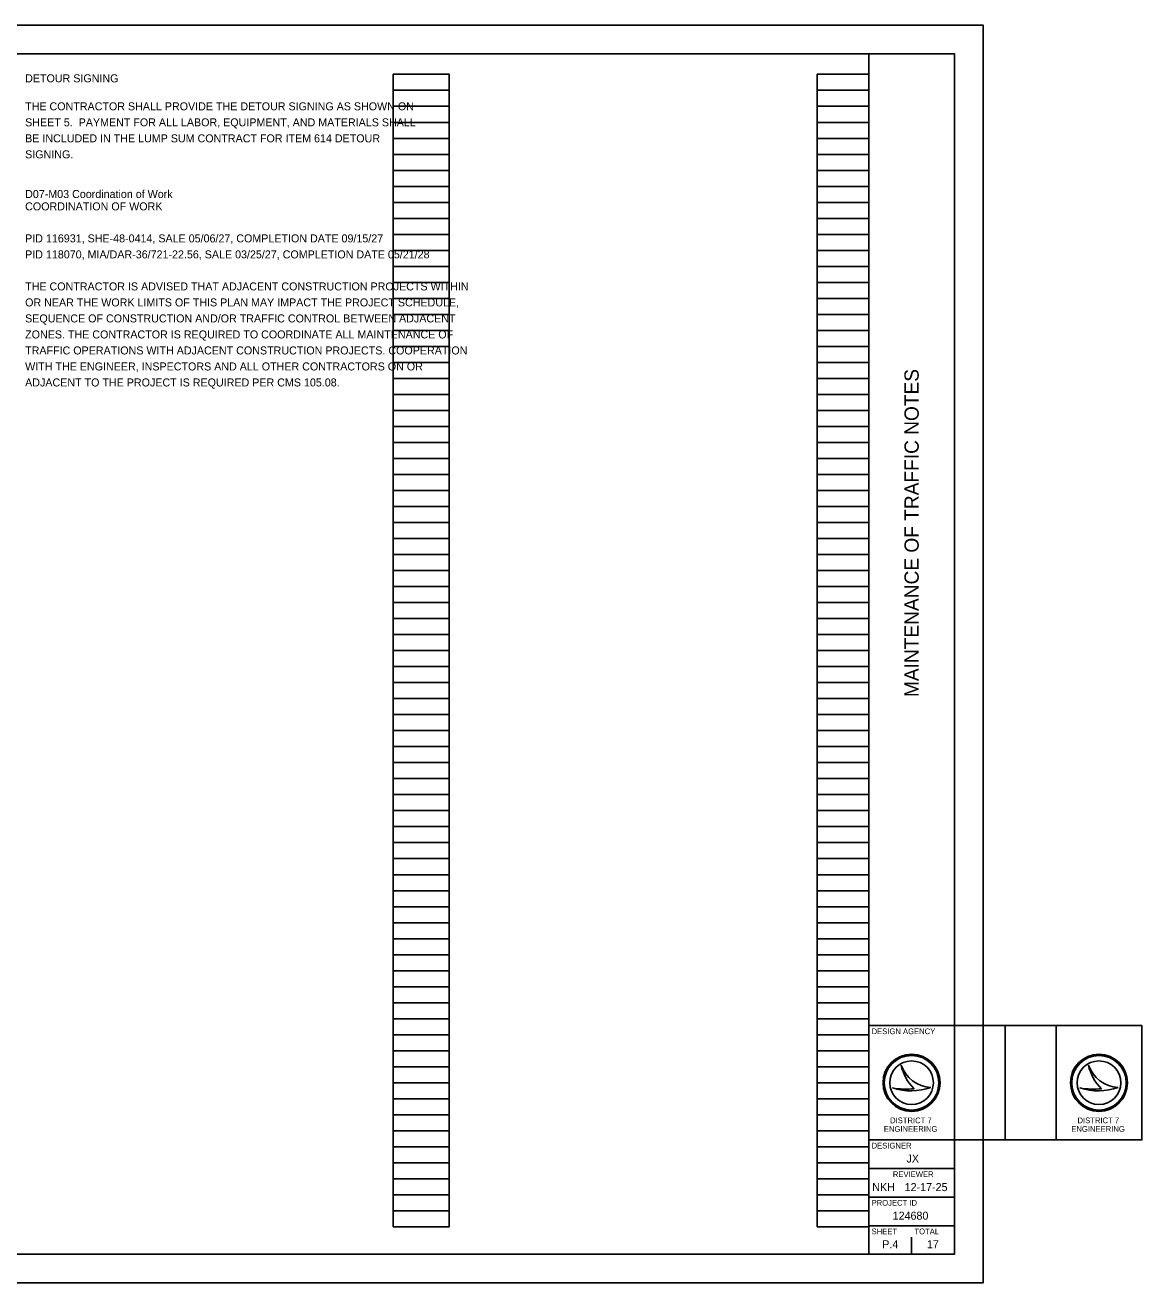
# Model space of a CAD drawing. Extents: x -9 to 36.8, y 0 to 22.
# Drawn here: x 17.24 to 36.78, y 0 to 22 of the extents above; entities that cross this region are included whole.
import ezdxf

# ---------------------------------------------------------------- set-up
doc = ezdxf.new("R2010")
doc.units = 0
for name, color, linetype in [('SC_Scratch1', 7, 'Continuous'), ('SH_Border', 7, 'Continuous'), ('SH_Cut_Line', 7, 'Continuous'), ('SH_Data', 7, 'Continuous'), ('SH_Text', 7, 'Continuous')]:
    doc.layers.add(name, color=color, linetype=linetype)

msp = doc.modelspace()

# ---------------------------------------------------------------- linework, layer by layer
at = {"layer": 'SC_Scratch1'}
for p, q in [((33.5, 4.5), (35.279, 4.5)), ((34.389, 4.5), (34.389, 2.5)), ((35.279, 2.5), (33.5, 2.5))]:
    msp.add_line(p, q, dxfattribs=at)
msp.add_lwpolyline([(35.279, 4.5), (36.779, 4.5), (36.779, 2.5), (35.279, 2.5)], close=True, dxfattribs=at)
at = {"layer": 'SH_Border'}
for p, q in [((32, 0.5), (32, 21.5)), ((32, 4.5), (33.5, 4.5)), ((32, 2.5), (33.5, 2.5)), ((32, 2), (33.5, 2)), ((32, 1.5), (33.5, 1.5)), ((32, 1), (33.5, 1))]:
    msp.add_line(p, q, dxfattribs=at)
msp.add_lwpolyline([(1.5, 21.5), (33.5, 21.5), (33.5, 0.5), (1.5, 0.5)], close=True, dxfattribs=at)
at = {"layer": 'SH_Cut_Line'}
msp.add_lwpolyline([(0, 0), (34, 0), (34, 22), (0, 22)], close=True, dxfattribs=at)
at = {"layer": 'SH_Data'}
for p, q in [((23.68, 0.98), (23.68, 21.14)), ((23.68, 21.14), (24.66, 21.14)), ((24.66, 0.98), (24.66, 21.14)), ((31.1, 0.98), (31.1, 21.14)), ((31.1, 21.14), (32, 21.14)), ((32, 0.98), (32, 21.14)), ((23.68, 20.86), (24.66, 20.86)), ((31.1, 20.86), (32, 20.86)), ((23.68, 20.58), (24.66, 20.58)), ((31.1, 20.58), (32, 20.58)), ((23.68, 20.3), (24.66, 20.3)), ((31.1, 20.3), (32, 20.3)), ((23.68, 20.02), (24.66, 20.02)), ((31.1, 20.02), (32, 20.02)), ((23.68, 19.74), (24.66, 19.74)), ((31.1, 19.74), (32, 19.74)), ((23.68, 19.46), (24.66, 19.46)), ((31.1, 19.46), (32, 19.46)), ((23.68, 19.18), (24.66, 19.18)), ((31.1, 19.18), (32, 19.18)), ((23.68, 18.9), (24.66, 18.9)), ((31.1, 18.9), (32, 18.9)), ((23.68, 18.62), (24.66, 18.62)), ((31.1, 18.62), (32, 18.62)), ((23.68, 18.34), (24.66, 18.34)), ((31.1, 18.34), (32, 18.34)), ((23.68, 18.06), (24.66, 18.06)), ((31.1, 18.06), (32, 18.06)), ((23.68, 17.78), (24.66, 17.78)), ((31.1, 17.78), (32, 17.78)), ((23.68, 17.5), (24.66, 17.5)), ((31.1, 17.5), (32, 17.5)), ((23.68, 17.22), (24.66, 17.22)), ((31.1, 17.22), (32, 17.22)), ((23.68, 16.94), (24.66, 16.94)), ((31.1, 16.94), (32, 16.94)), ((23.68, 16.66), (24.66, 16.66)), ((31.1, 16.66), (32, 16.66)), ((23.68, 16.38), (24.66, 16.38)), ((31.1, 16.38), (32, 16.38)), ((23.68, 16.1), (24.66, 16.1)), ((31.1, 16.1), (32, 16.1)), ((23.68, 15.82), (24.66, 15.82)), ((31.1, 15.82), (32, 15.82)), ((23.68, 15.54), (24.66, 15.54)), ((31.1, 15.54), (32, 15.54)), ((23.68, 15.26), (24.66, 15.26)), ((31.1, 15.26), (32, 15.26)), ((23.68, 14.98), (24.66, 14.98)), ((31.1, 14.98), (32, 14.98)), ((23.68, 14.7), (24.66, 14.7)), ((31.1, 14.7), (32, 14.7)), ((23.68, 14.42), (24.66, 14.42)), ((31.1, 14.42), (32, 14.42)), ((23.68, 14.14), (24.66, 14.14)), ((31.1, 14.14), (32, 14.14)), ((23.68, 13.86), (24.66, 13.86)), ((31.1, 13.86), (32, 13.86)), ((23.68, 13.58), (24.66, 13.58)), ((31.1, 13.58), (32, 13.58)), ((23.68, 13.3), (24.66, 13.3)), ((31.1, 13.3), (32, 13.3)), ((23.68, 13.02), (24.66, 13.02)), ((31.1, 13.02), (32, 13.02)), ((23.68, 12.74), (24.66, 12.74)), ((31.1, 12.74), (32, 12.74)), ((23.68, 12.46), (24.66, 12.46)), ((31.1, 12.46), (32, 12.46)), ((23.68, 12.18), (24.66, 12.18)), ((31.1, 12.18), (32, 12.18)), ((23.68, 11.9), (24.66, 11.9)), ((31.1, 11.9), (32, 11.9)), ((23.68, 11.62), (24.66, 11.62)), ((31.1, 11.62), (32, 11.62)), ((23.68, 11.34), (24.66, 11.34)), ((31.1, 11.34), (32, 11.34)), ((23.68, 11.06), (24.66, 11.06)), ((31.1, 11.06), (32, 11.06)), ((23.68, 10.78), (24.66, 10.78)), ((31.1, 10.78), (32, 10.78)), ((23.68, 10.5), (24.66, 10.5)), ((31.1, 10.5), (32, 10.5)), ((23.68, 10.22), (24.66, 10.22)), ((31.1, 10.22), (32, 10.22)), ((23.68, 9.94), (24.66, 9.94)), ((31.1, 9.94), (32, 9.94)), ((23.68, 9.66), (24.66, 9.66)), ((31.1, 9.66), (32, 9.66)), ((23.68, 9.38), (24.66, 9.38)), ((31.1, 9.38), (32, 9.38)), ((23.68, 9.1), (24.66, 9.1)), ((31.1, 9.1), (32, 9.1)), ((23.68, 8.82), (24.66, 8.82)), ((31.1, 8.82), (32, 8.82)), ((23.68, 8.54), (24.66, 8.54)), ((31.1, 8.54), (32, 8.54)), ((23.68, 8.26), (24.66, 8.26)), ((31.1, 8.26), (32, 8.26)), ((23.68, 7.98), (24.66, 7.98)), ((31.1, 7.98), (32, 7.98)), ((23.68, 7.7), (24.66, 7.7)), ((31.1, 7.7), (32, 7.7)), ((23.68, 7.42), (24.66, 7.42)), ((31.1, 7.42), (32, 7.42)), ((23.68, 7.14), (24.66, 7.14)), ((31.1, 7.14), (32, 7.14)), ((23.68, 6.86), (24.66, 6.86)), ((31.1, 6.86), (32, 6.86)), ((23.68, 6.58), (24.66, 6.58)), ((31.1, 6.58), (32, 6.58)), ((23.68, 6.3), (24.66, 6.3)), ((31.1, 6.3), (32, 6.3)), ((23.68, 6.02), (24.66, 6.02)), ((31.1, 6.02), (32, 6.02)), ((23.68, 5.74), (24.66, 5.74)), ((31.1, 5.74), (32, 5.74)), ((23.68, 5.46), (24.66, 5.46)), ((31.1, 5.46), (32, 5.46)), ((23.68, 5.18), (24.66, 5.18)), ((31.1, 5.18), (32, 5.18)), ((23.68, 4.9), (24.66, 4.9)), ((31.1, 4.9), (32, 4.9)), ((23.68, 4.62), (24.66, 4.62)), ((31.1, 4.62), (32, 4.62)), ((23.68, 4.34), (24.66, 4.34)), ((31.1, 4.34), (32, 4.34)), ((23.68, 4.06), (24.66, 4.06)), ((31.1, 4.06), (32, 4.06)), ((23.68, 3.78), (24.66, 3.78)), ((31.1, 3.78), (32, 3.78)), ((32.567, 3.81), (32.567, 3.81)), ((35.846, 3.81), (35.846, 3.81)), ((23.68, 3.5), (24.66, 3.5)), ((31.1, 3.5), (32, 3.5)), ((32.417, 3.41), (32.417, 3.41)), ((32.75, 3.5), (32.75, 3.5)), ((33.087, 3.419), (33.087, 3.419)), ((35.696, 3.41), (35.696, 3.41)), ((36.366, 3.419), (36.366, 3.419)), ((23.68, 3.22), (24.66, 3.22)), ((31.1, 3.22), (32, 3.22)), ((23.68, 2.94), (24.66, 2.94)), ((31.1, 2.94), (32, 2.94)), ((23.68, 2.66), (24.66, 2.66)), ((31.1, 2.66), (32, 2.66)), ((23.68, 2.38), (24.66, 2.38)), ((31.1, 2.38), (32, 2.38)), ((23.68, 2.1), (24.66, 2.1)), ((31.1, 2.1), (32, 2.1)), ((23.68, 1.82), (24.66, 1.82)), ((31.1, 1.82), (32, 1.82)), ((23.68, 1.54), (24.66, 1.54)), ((31.1, 1.54), (32, 1.54)), ((23.68, 1.26), (24.66, 1.26)), ((31.1, 1.26), (32, 1.26)), ((23.68, 0.98), (24.66, 0.98)), ((31.1, 0.98), (32, 0.98)), ((32.375, 0.675), (32.375, 0.675)), ((32.75, 0.5), (32.75, 0.8))]:
    msp.add_line(p, q, dxfattribs=at)
for centre, radius in [((32.75, 3.5), 0.5), ((32.75, 3.5), 0.477), ((32.75, 3.5), 0.477), ((36.029, 3.5), 0.5), ((36.029, 3.5), 0.477), ((36.029, 3.5), 0.477), ((32.75, 3.5), 0.382), ((36.029, 3.5), 0.382)]:
    msp.add_circle(centre, radius, dxfattribs=at)
for centre, radius, start, end in [((33.116, 3.998), 0.58, 198.9257, 198.9319), ((33.347, 3.97), 0.796, 191.6379, 191.6421), ((33.116, 3.998), 0.58, 198.9319, 267.1657), ((33.347, 3.97), 0.796, 191.6421, 226.0947), ((36.395, 3.998), 0.58, 198.9257, 198.9319), ((36.625, 3.97), 0.796, 191.6379, 191.6421), ((36.395, 3.998), 0.58, 198.9319, 267.1657), ((36.625, 3.97), 0.796, 191.6421, 226.0947), ((32.739, 4.37), 1.013, 251.4576, 290.0832), ((32.648, 4.654), 1.266, 259.4964, 259.4995), ((32.739, 4.37), 1.013, 251.4527, 251.4576), ((32.648, 4.654), 1.266, 259.4995, 276.6672), ((36.018, 4.37), 1.013, 251.4576, 290.0832), ((35.927, 4.654), 1.266, 259.4964, 259.4995), ((36.018, 4.37), 1.013, 251.4527, 251.4576), ((35.927, 4.654), 1.266, 259.4995, 276.6672)]:
    msp.add_arc(centre, radius, start, end, dxfattribs=at)

# ---------------------------------------------------------------- texts
at = {"layer": 'SC_Scratch1'}
msp.add_text('D07-M03 Coordination of Work', height=0.14, dxfattribs=at).set_placement((17.24, 18.976))
at = {"layer": 'SH_Data'}
msp.add_text('MAINTENANCE OF TRAFFIC NOTES', height=0.25, rotation=90, dxfattribs=at).set_placement((32.875, 10.247))
for s, height, p in [('DESIGN AGENCY', 0.1, (32.05, 4.35)), ('DESIGNER', 0.1, (32.05, 2.35)), ('JX', 0.14, (32.661, 2.105)), ('REVIEWER', 0.1, (32.422, 1.85)), ('NKH', 0.14, (32.062, 1.605)), ('12-17-25', 0.14, (32.629, 1.605)), ('PROJECT ID', 0.1, (32.05, 1.35)), ('124680', 0.14, (32.419, 1.105)), ('SHEET', 0.1, (32.05, 0.85)), ('TOTAL', 0.1, (32.8, 0.85)), ('P.4', 0.14, (32.237, 0.605)), ('17', 0.14, (33.018, 0.605))]:
    msp.add_text(s, height=height, dxfattribs=at).set_placement(p)
at = {"layer": 'SH_Text'}
for s, height, p in [('DETOUR SIGNING', 0.14, (17.24, 21)), ('THE CONTRACTOR SHALL PROVIDE THE DETOUR SIGNING AS SHOWN ON ', 0.14, (17.24, 20.51)), ('SHEET 5.  PAYMENT FOR ALL LABOR, EQUIPMENT, AND MATERIALS SHALL ', 0.14, (17.24, 20.23)), ('BE INCLUDED IN THE LUMP SUM CONTRACT FOR ITEM 614 DETOUR ', 0.14, (17.24, 19.95)), ('SIGNING.', 0.14, (17.24, 19.67)), ('COORDINATION OF WORK', 0.14, (17.24, 18.76)), ('PID 116931, SHE-48-0414, SALE 05/06/27, COMPLETION DATE 09/15/27', 0.14, (17.24, 18.2)), ('PID 118070, MIA/DAR-36/721-22.56, SALE 03/25/27, COMPLETION DATE 05/21/28', 0.14, (17.24, 17.92)), ('THE CONTRACTOR IS ADVISED THAT ADJACENT CONSTRUCTION PROJECTS WITHIN ', 0.14, (17.24, 17.36)), ('OR NEAR THE WORK LIMITS OF THIS PLAN MAY IMPACT THE PROJECT SCHEDULE, ', 0.14, (17.24, 17.08)), ('SEQUENCE OF CONSTRUCTION AND/OR TRAFFIC CONTROL BETWEEN ADJACENT ', 0.14, (17.24, 16.8)), ('ZONES. THE CONTRACTOR IS REQUIRED TO COORDINATE ALL MAINTENANCE OF ', 0.14, (17.24, 16.52)), ('TRAFFIC OPERATIONS WITH ADJACENT CONSTRUCTION PROJECTS. COOPERATION ', 0.14, (17.24, 16.24)), ('WITH THE ENGINEER, INSPECTORS AND ALL OTHER CONTRACTORS ON OR ', 0.14, (17.24, 15.96)), ('ADJACENT TO THE PROJECT IS REQUIRED PER CMS 105.08.', 0.14, (17.24, 15.68)), ('DISTRICT 7', 0.1, (32.374, 2.792)), ('DISTRICT 7', 0.1, (35.653, 2.792)), ('ENGINEERING', 0.1, (32.265, 2.642)), ('ENGINEERING', 0.1, (35.544, 2.642))]:
    msp.add_text(s, height=height, dxfattribs=at).set_placement(p)

doc.saveas('drawing.dxf')
